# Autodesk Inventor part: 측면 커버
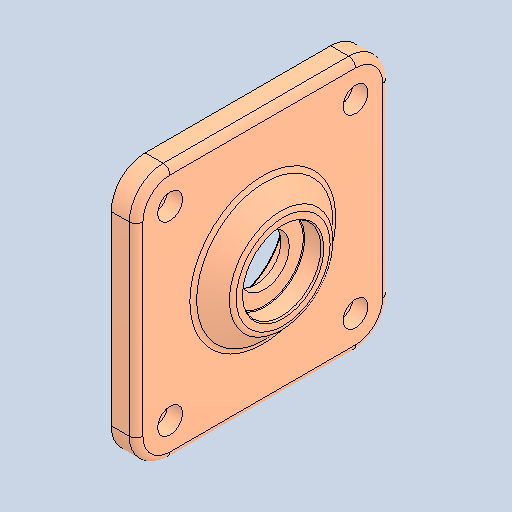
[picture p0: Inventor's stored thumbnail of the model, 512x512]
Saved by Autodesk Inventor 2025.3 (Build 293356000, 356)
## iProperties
Created: 2026-01
Part Number: 측면 커버
Material: 알루미늄 6061
Document SubType Name: Modeling
Designer: pc6
Density: 2.7 g/cm^3
Appearance: 기본값
Author: jhkim
Sending System: Autodesk Inventor 2026
Preprocessor: ST-DEVELOPER v20.1
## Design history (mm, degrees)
feature "솔리드1"
node "솔리드2"
